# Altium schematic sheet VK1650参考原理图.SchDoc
size A4
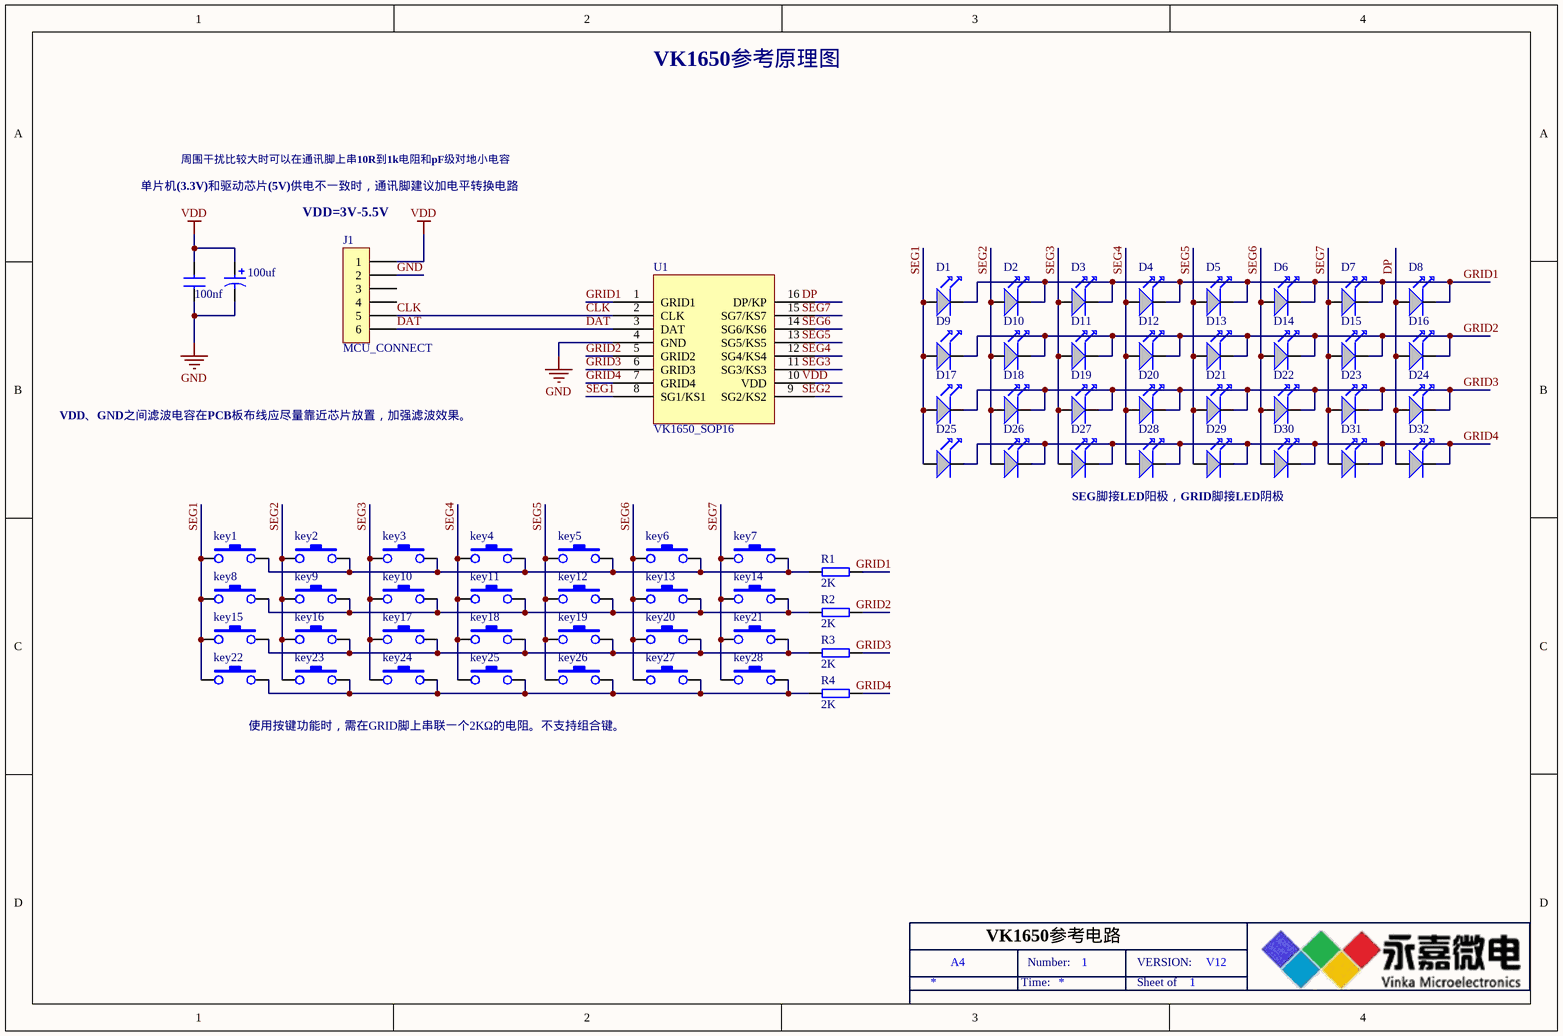
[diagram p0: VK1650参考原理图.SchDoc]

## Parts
100nf  CAP  (value not drawn)
100uf  CAP2  (value not drawn)
D1  (no value)  [1206-LED]
D2  (no value)  [1206-LED]
D3  (no value)  [1206-LED]
D4  (no value)  [1206-LED]
D5  (no value)  [1206-LED]
D6  (no value)  [1206-LED]
D7  (no value)  [1206-LED]
D8  (no value)  [1206-LED]
D9  (no value)  [1206-LED]
D10  (no value)  [1206-LED]
D11  (no value)  [1206-LED]
D12  (no value)  [1206-LED]
D13  (no value)  [1206-LED]
D14  (no value)  [1206-LED]
D15  (no value)  [1206-LED]
D16  (no value)  [1206-LED]
D17  (no value)  [1206-LED]
D18  (no value)  [1206-LED]
D19  (no value)  [1206-LED]
D20  (no value)  [1206-LED]
D21  (no value)  [1206-LED]
D22  (no value)  [1206-LED]
D23  (no value)  [1206-LED]
D24  (no value)  [1206-LED]
D25  (no value)  [1206-LED]
D26  (no value)  [1206-LED]
D27  (no value)  [1206-LED]
D28  (no value)  [1206-LED]
D29  (no value)  [1206-LED]
D30  (no value)  [1206-LED]
D31  (no value)  [1206-LED]
D32  (no value)  [1206-LED]
J1  MCU_CONNECT
key1  (no value)  [AN12]
key2  (no value)  [AN12]
key3  KEY  [AN12]  (value not drawn)
key4  (no value)  [AN12]
key5  (no value)  [AN12]
key6  (no value)  [AN12]
key7  (no value)  [AN12]
key8  (no value)  [AN12]
key9  (no value)  [AN12]
key10  KEY  [AN12]  (value not drawn)
key11  (no value)  [AN12]
key12  (no value)  [AN12]
key13  (no value)  [AN12]
key14  (no value)  [AN12]
key15  (no value)  [AN12]
key16  (no value)  [AN12]
key17  KEY  [AN12]  (value not drawn)
key18  (no value)  [AN12]
key19  (no value)  [AN12]
key20  (no value)  [AN12]
key21  (no value)  [AN12]
key22  (no value)  [AN12]
key23  (no value)  [AN12]
key24  KEY  [AN12]  (value not drawn)
key25  (no value)  [AN12]
key26  (no value)  [AN12]
key27  (no value)  [AN12]
key28  (no value)  [AN12]
R1  2K  [0603-R]
R2  2K  [0603-R]
R3  2K  [0603-R]
R4  2K  [0603-R]
U1  VK1650_SOP16

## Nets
GND: 100nf.2 100uf.2 J1.2 U1.4(GND)
VDD: 100nf.1 100uf.1 J1.1
CLK: J1.5 U1.2(CLK)
DAT: J1.6 U1.3(DAT)
DP: D8.1 D16.1 D24.1 D32.1
GRID1: D1.2 D2.2 D3.2 D4.2 D5.2 D6.2 D7.2 D8.2 U1.1(GRID1)
GRID2: D9.2 D10.2 D11.2 D12.2 D13.2 D14.2 D15.2 D16.2 U1.5(GRID2)
GRID3: D17.2 D18.2 D19.2 D20.2 D21.2 D22.2 D23.2 D24.2 U1.6(GRID3)
GRID4: D25.2 D26.2 D27.2 D28.2 D29.2 D30.2 D31.2 D32.2 U1.7(GRID4)
SEG1: D1.1 D9.1 D17.1 D25.1 key1.1 key8.1 key15.1 key22.1 U1.8(SG1/KS1)
SEG2: D2.1 D10.1 D18.1 D26.1 key2.1 key9.1 key16.1 key23.1
SEG3: D3.1 D11.1 D19.1 D27.1 key3.1 key10.1 key17.1 key24.1
SEG4: D4.1 D12.1 D20.1 D28.1 key4.1 key11.1 key18.1 key25.1
SEG5: D5.1 D13.1 D21.1 D29.1 key5.1 key12.1 key19.1 key26.1
SEG6: D6.1 D14.1 D22.1 D30.1 key6.1 key13.1 key20.1 key27.1
SEG7: D7.1 D15.1 D23.1 D31.1 key7.1 key14.1 key21.1 key28.1
Netkey1_2: key1.2 key2.2 key3.2 key4.2 key5.2 key6.2 key7.2 R1.1
Netkey8_2: key8.2 key9.2 key10.2 key11.2 key12.2 key13.2 key14.2 R2.1
Netkey15_2: key15.2 key16.2 key17.2 key18.2 key19.2 key20.2 key21.2 R3.1
Netkey22_2: key22.2 key23.2 key24.2 key25.2 key26.2 key27.2 key28.2 R4.1

Not connected (* = marked no-connect by the designer): J1 3 4; R1 2; R2 2; R3 2; R4 2; U1 9(SG2/KS2) 10(VDD) 11(SG3/KS3) 12(SG4/KS4) 13(SG5/KS5) 14(SG6/KS6) 15(SG7/KS7) 16(DP/KP)

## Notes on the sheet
- VK1650参考原理图
- 周围干扰比较大时可以在通讯脚上串10R到1k电阻和pF级对地小电容
- 单片机(3.3V)和驱动芯片(5V)供电不一致时，通讯脚建议加电平转换电路
- (near J1) VDD=3V-5.5V
- VDD、GND之间滤波电容在PCB板布线应尽量靠近芯片放置，加强滤波效果。
- SEG脚接LED阳极，GRID脚接LED阴极
- 使用按键功能时，需在GRID脚上串联一个2KΩ的电阻。不支持组合键。
- A4
- VK1650参考电路
- Time:
- Number:
- 1
- Sheet of
- VERSION:
- V12
- Labels drawn without touching a wire or pin: DP, GRID1, GRID2, GRID3, GRID4, SEG2, SEG3, SEG4, SEG5, SEG6, SEG7, VDD

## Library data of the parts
100nf = CAP: Capacitor
100uf = CAP2: Bi-Polar Capacitor
D1-D32 = LED: Text Field1: 30; Text Field2: 20
J1 = CON6: Connector
key1 key2 key4-key9 key11-key16 key18-key23 key25-key28 = KEY
R1-R4 = RES: Resistor
U1 = VK1650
